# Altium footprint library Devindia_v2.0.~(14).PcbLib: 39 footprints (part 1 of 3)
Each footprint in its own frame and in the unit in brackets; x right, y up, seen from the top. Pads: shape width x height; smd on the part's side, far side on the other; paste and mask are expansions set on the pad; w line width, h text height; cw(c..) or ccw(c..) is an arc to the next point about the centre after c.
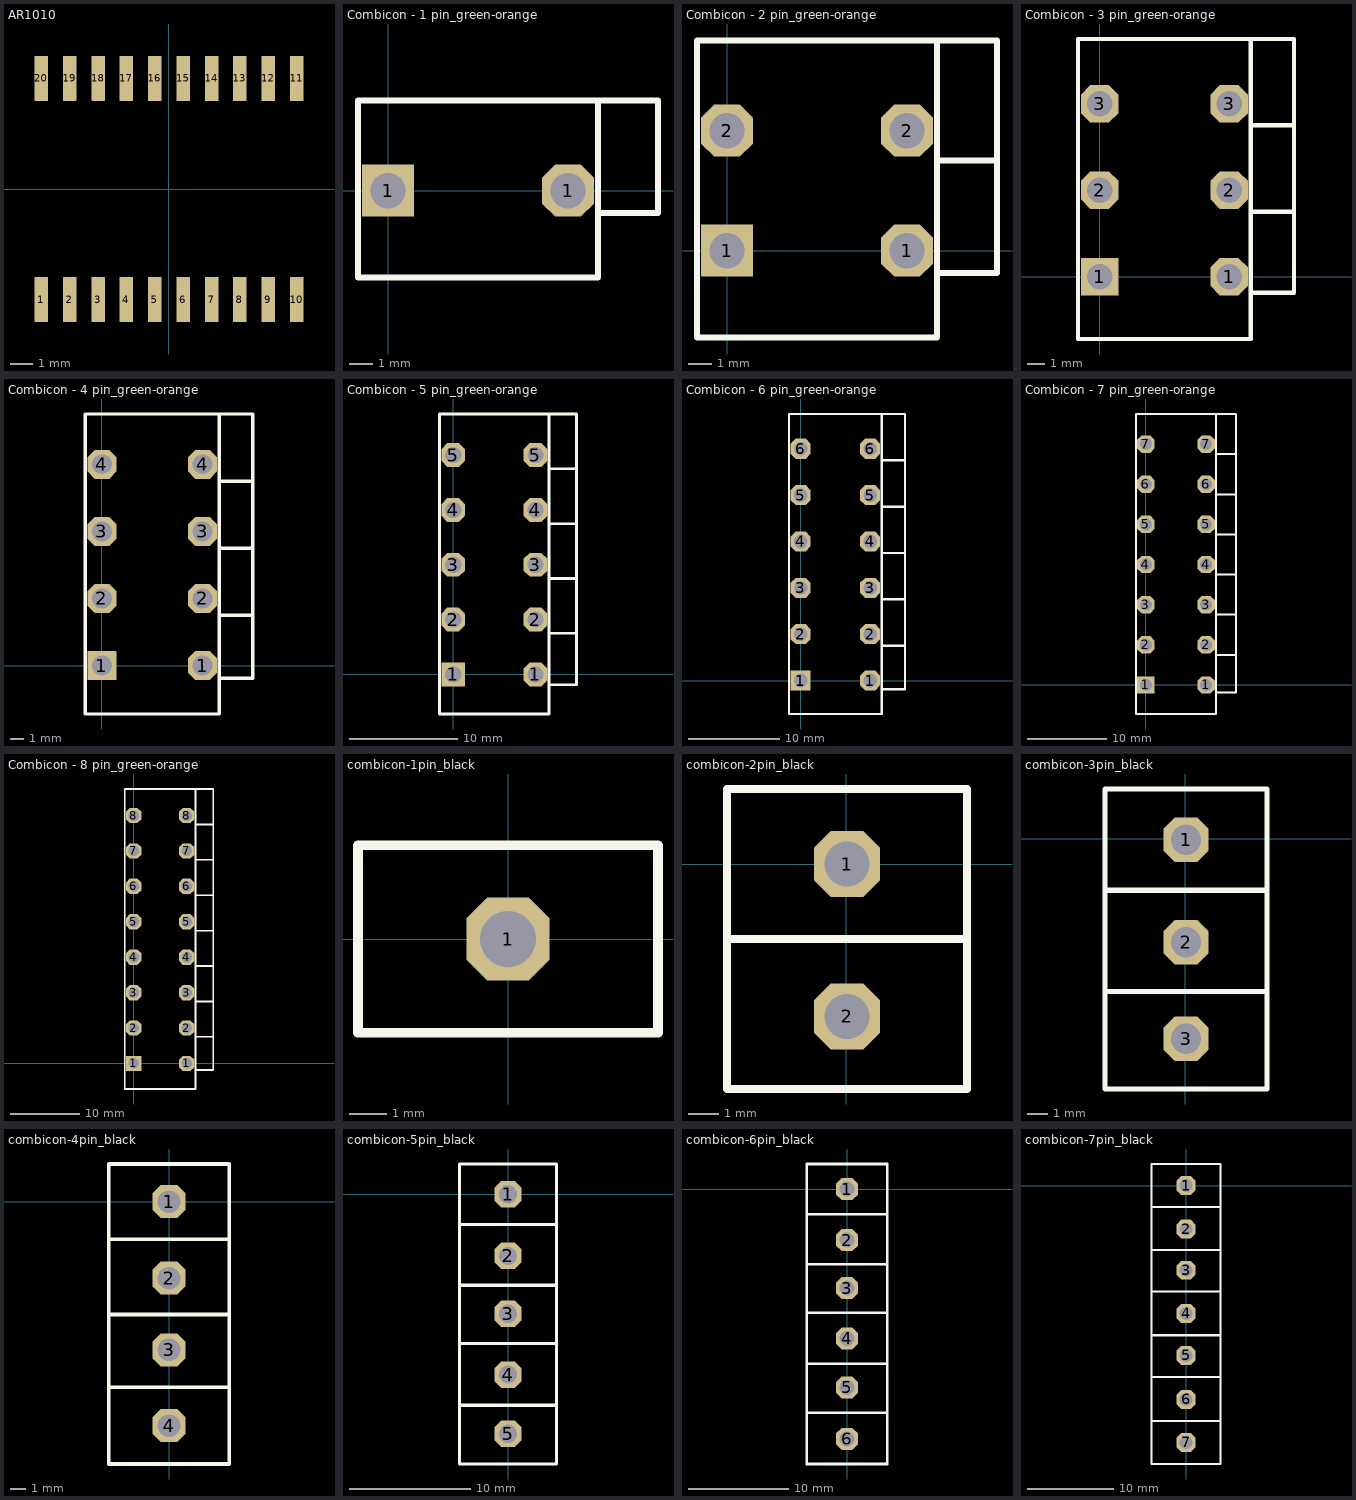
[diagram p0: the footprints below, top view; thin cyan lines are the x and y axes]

## AR1010 [mm]
pads (20):
  rect 0.6x2 smd: 1(-5.715,-4.95) 2(-4.445,-4.95) 3(-3.175,-4.95) 4(-1.905,-4.95) 5(-0.635,-4.95) 6(0.635,-4.95) 7(1.905,-4.95) 8(3.175,-4.95) 9(4.445,-4.95) 10(5.715,-4.95) 11(5.715,4.95) 12(4.445,4.95) 13(3.175,4.95) 14(1.905,4.95) 15(0.635,4.95) 16(-0.635,4.95) 17(-1.905,4.95) 18(-3.175,4.95) 19(-4.445,4.95) 20(-5.715,4.95)
Bottom Overlay:
  circle w0.254: c-5.695,-3.115 r0.284
  lines w0.254: -6.4,-3.75 6.4,-3.75 6.4,3.75 -6.4,3.75 -6.4,-3.75
3D body: height 2.05, standoff 1.05, extent -6.35,-3.175 6.35,3.175
3D body: height 1.18, standoff 0.1, extent -6.35,-3.81 6.35,3.81
3D body: height 1.16, standoff 0.84, extent -5.969,4.126 -5.461,4.445
3D body: height 0.32, standoff 0, extent -5.969,4.191 -5.461,4.51
3D body: height 1.16, standoff 0.84, extent -5.969,3.175 -5.461,4.318
3D body: height 1, standoff 0.16, extent -5.969,4.191 -5.461,4.445
3D body: height 0.32, standoff 0, extent -5.969,4.318 -5.461,5.588
3D body: height 1.16, standoff 0.84, extent -4.699,4.126 -4.191,4.445
3D body: height 0.32, standoff 0, extent -4.699,4.191 -4.191,4.51
3D body: height 1.16, standoff 0.84, extent -4.699,3.175 -4.191,4.318
3D body: height 1, standoff 0.16, extent -4.699,4.191 -4.191,4.445
3D body: height 0.32, standoff 0, extent -4.699,4.318 -4.191,5.588
3D body: height 1.16, standoff 0.84, extent -3.429,3.175 -2.921,4.318
3D body: height 1.16, standoff 0.84, extent -3.429,4.126 -2.921,4.445
3D body: height 0.32, standoff 0, extent -3.429,4.191 -2.921,4.51
3D body: height 1, standoff 0.16, extent -3.429,4.191 -2.921,4.445
3D body: height 0.32, standoff 0, extent -3.429,4.318 -2.921,5.588
3D body: height 1.16, standoff 0.84, extent -2.159,3.175 -1.651,4.318
3D body: height 1.16, standoff 0.84, extent -2.159,4.126 -1.651,4.445
3D body: height 0.32, standoff 0, extent -2.159,4.191 -1.651,4.51
3D body: height 1, standoff 0.16, extent -2.159,4.191 -1.651,4.445
3D body: height 0.32, standoff 0, extent -2.159,4.318 -1.651,5.588
3D body: height 1.16, standoff 0.84, extent -0.889,3.175 -0.381,4.318
3D body: height 1.16, standoff 0.84, extent -0.889,4.126 -0.381,4.445
3D body: height 0.32, standoff 0, extent -0.889,4.191 -0.381,4.51
3D body: height 1, standoff 0.16, extent -0.889,4.191 -0.381,4.445
3D body: height 0.32, standoff 0, extent -0.889,4.318 -0.381,5.588
3D body: height 1.16, standoff 0.84, extent 0.381,3.175 0.889,4.318
3D body: height 1.16, standoff 0.84, extent 0.381,4.126 0.889,4.445
3D body: height 0.32, standoff 0, extent 0.381,4.191 0.889,4.51
3D body: height 1, standoff 0.16, extent 0.381,4.191 0.889,4.445
3D body: height 0.32, standoff 0, extent 0.381,4.318 0.889,5.588
3D body: height 1.16, standoff 0.84, extent 1.651,3.175 2.159,4.318
3D body: height 1.16, standoff 0.84, extent 1.651,4.126 2.159,4.445
3D body: height 0.32, standoff 0, extent 1.651,4.191 2.159,4.51
3D body: height 1, standoff 0.16, extent 1.651,4.191 2.159,4.445
3D body: height 0.32, standoff 0, extent 1.651,4.318 2.159,5.588
3D body: height 1.16, standoff 0.84, extent 2.921,3.175 3.429,4.318
3D body: height 1.16, standoff 0.84, extent 2.921,4.126 3.429,4.445
3D body: height 0.32, standoff 0, extent 2.921,4.191 3.429,4.51
3D body: height 1, standoff 0.16, extent 2.921,4.191 3.429,4.445
3D body: height 0.32, standoff 0, extent 2.921,4.318 3.429,5.588
3D body: height 1.16, standoff 0.84, extent 4.191,3.175 4.699,4.318
3D body: height 1.16, standoff 0.84, extent 4.191,4.126 4.699,4.445
3D body: height 0.32, standoff 0, extent 4.191,4.191 4.699,4.51
3D body: height 1, standoff 0.16, extent 4.191,4.191 4.699,4.445
3D body: height 0.32, standoff 0, extent 4.191,4.318 4.699,5.588
3D body: height 1.16, standoff 0.84, extent 5.461,3.175 5.969,4.318
3D body: height 1.16, standoff 0.84, extent 5.461,4.126 5.969,4.445
3D body: height 0.32, standoff 0, extent 5.461,4.191 5.969,4.51
3D body: height 1, standoff 0.16, extent 5.461,4.191 5.969,4.445
3D body: height 0.32, standoff 0, extent 5.461,4.318 5.969,5.588
3D body: height 1.16, standoff 0.84, extent 5.461,-4.318 5.969,-3.175
3D body: height 1.16, standoff 0.84, extent 5.461,-4.445 5.969,-4.126
3D body: height 0.32, standoff 0, extent 5.461,-4.51 5.969,-4.191
3D body: height 1, standoff 0.16, extent 5.461,-4.445 5.969,-4.191
3D body: height 0.32, standoff 0, extent 5.461,-5.588 5.969,-4.318
3D body: height 1.16, standoff 0.84, extent 4.191,-4.318 4.699,-3.175
3D body: height 1.16, standoff 0.84, extent 4.191,-4.445 4.699,-4.126
3D body: height 0.32, standoff 0, extent 4.191,-4.51 4.699,-4.191
3D body: height 1, standoff 0.16, extent 4.191,-4.445 4.699,-4.191
3D body: height 0.32, standoff 0, extent 4.191,-5.588 4.699,-4.318
3D body: height 1.16, standoff 0.84, extent 2.921,-4.318 3.429,-3.175
3D body: height 1.16, standoff 0.84, extent 2.921,-4.445 3.429,-4.126
3D body: height 0.32, standoff 0, extent 2.921,-4.51 3.429,-4.191
3D body: height 1, standoff 0.16, extent 2.921,-4.445 3.429,-4.191
3D body: height 0.32, standoff 0, extent 2.921,-5.588 3.429,-4.318
3D body: height 1.16, standoff 0.84, extent 1.651,-4.318 2.159,-3.175
3D body: height 1.16, standoff 0.84, extent 1.651,-4.445 2.159,-4.126
3D body: height 0.32, standoff 0, extent 1.651,-4.51 2.159,-4.191
3D body: height 1, standoff 0.16, extent 1.651,-4.445 2.159,-4.191
3D body: height 0.32, standoff 0, extent 1.651,-5.588 2.159,-4.318
3D body: height 1.16, standoff 0.84, extent 0.381,-4.318 0.889,-3.175
3D body: height 1.16, standoff 0.84, extent 0.381,-4.445 0.889,-4.126
3D body: height 0.32, standoff 0, extent 0.381,-4.51 0.889,-4.191
3D body: height 1, standoff 0.16, extent 0.381,-4.445 0.889,-4.191
3D body: height 0.32, standoff 0, extent 0.381,-5.588 0.889,-4.318
3D body: height 1.16, standoff 0.84, extent -0.889,-4.318 -0.381,-3.175
3D body: height 1.16, standoff 0.84, extent -0.889,-4.445 -0.381,-4.126
3D body: height 0.32, standoff 0, extent -0.889,-4.51 -0.381,-4.191
3D body: height 1, standoff 0.16, extent -0.889,-4.445 -0.381,-4.191
3D body: height 0.32, standoff 0, extent -0.889,-5.588 -0.381,-4.318
3D body: height 1.16, standoff 0.84, extent -2.159,-4.318 -1.651,-3.175
3D body: height 1.16, standoff 0.84, extent -2.159,-4.445 -1.651,-4.126
3D body: height 0.32, standoff 0, extent -2.159,-4.51 -1.651,-4.191
3D body: height 1, standoff 0.16, extent -2.159,-4.445 -1.651,-4.191
3D body: height 0.32, standoff 0, extent -2.159,-5.588 -1.651,-4.318
3D body: height 1.16, standoff 0.84, extent -3.429,-4.318 -2.921,-3.175
3D body: height 1.16, standoff 0.84, extent -3.429,-4.445 -2.921,-4.126
3D body: height 0.32, standoff 0, extent -3.429,-4.51 -2.921,-4.191
3D body: height 1, standoff 0.16, extent -3.429,-4.445 -2.921,-4.191
3D body: height 0.32, standoff 0, extent -3.429,-5.588 -2.921,-4.318
3D body: height 1.16, standoff 0.84, extent -4.699,-4.318 -4.191,-3.175
3D body: height 1.16, standoff 0.84, extent -4.699,-4.445 -4.191,-4.126
3D body: height 0.32, standoff 0, extent -4.699,-4.51 -4.191,-4.191
3D body: height 1, standoff 0.16, extent -4.699,-4.445 -4.191,-4.191
3D body: height 0.32, standoff 0, extent -4.699,-5.588 -4.191,-4.318
3D body: height 1.16, standoff 0.84, extent -5.969,-4.318 -5.461,-3.175
3D body: height 1.16, standoff 0.84, extent -5.969,-4.445 -5.461,-4.126
3D body: height 0.32, standoff 0, extent -5.969,-4.51 -5.461,-4.191
3D body: height 1, standoff 0.16, extent -5.969,-4.445 -5.461,-4.191
3D body: height 0.32, standoff 0, extent -5.969,-5.588 -5.461,-4.318
3D body: height 2.15, standoff 2.05, extent -5.969,-2.54 -5.46,-2.034

## Combicon - 1 pin_green-orange [mm]
pads (2):
  rect 2.2x2.2 hole 1.5: 1(0,0)
  oct 2.2x2.2 hole 1.5: 1(7.62,0)
Top Overlay:
  lines w0.254: 8.956,-0.95 11.43,-0.95 11.43,3.81 8.89,3.81 ; 8.89,3.81 -1.27,3.81 -1.27,0.07 -1.27,-3.67 8.89,-3.67 8.89,3.81
3D body: height 13.66, standoff 7.75, extent 8.89,-1.016 11.43,3.81
3D body: height 13.5, standoff 13, extent 5.969,-1.503 8.864,1.397
3D body: height 13, standoff 0, extent -1.27,-3.683 8.89,3.81

## Combicon - 2 pin_green-orange [mm]
pads (4):
  rect 2.2x2.2 hole 1.5: 1(0,0)
  oct 2.2x2.2 hole 1.5: 1(7.62,0) 2(0,5.08) 2(7.62,5.08)
Top Overlay:
  lines w0.254: 8.956,-0.95 11.43,-0.95 11.43,3.81 ; 8.89,3.81 8.89,8.89 ; 8.89,3.81 8.89,-3.67 -1.27,-3.67 -1.27,0.07 -1.27,8.89 8.89,8.89 ; 8.89,3.81 11.43,3.81 ; 8.89,8.89 11.43,8.89 11.43,3.81
3D body: height 13, standoff 0, extent -1.27,-3.683 8.89,8.89
3D body: height 13.5, standoff 13, extent 5.969,-1.503 8.864,1.397
3D body: height 13.5, standoff 13, extent 5.969,3.577 8.864,6.477
3D body: height 13.66, standoff 7.75, extent 8.89,4.064 11.43,8.89
3D body: height 13.66, standoff 7.75, extent 8.89,-1.016 11.43,3.81

## Combicon - 3 pin_green-orange [mm]
pads (6):
  rect 2.2x2.2 hole 1.5: 1(0,0)
  oct 2.2x2.2 hole 1.5: 1(7.62,0) 2(0,5.08) 2(7.62,5.08) 3(0,10.16) 3(7.62,10.16)
Top Overlay:
  lines w0.254: 8.89,8.89 11.43,8.89 ; 8.956,-0.95 11.43,-0.95 11.43,3.81 ; 8.89,3.81 8.89,13.97 ; 8.89,3.81 8.89,-3.67 -1.27,-3.67 -1.27,0.07 -1.27,13.97 8.89,13.97 ; 8.89,3.81 11.43,3.81 ; 8.89,13.97 11.43,13.97 11.43,8.89 ; 11.43,3.81 11.43,8.89
3D body: height 13, standoff 0, extent -1.27,-3.683 8.89,13.97
3D body: height 13.5, standoff 13, extent 5.969,-1.503 8.864,1.397
3D body: height 13.5, standoff 13, extent 5.969,3.577 8.864,6.477
3D body: height 13.5, standoff 13, extent 5.969,8.657 8.864,11.557
3D body: height 13.66, standoff 7.75, extent 8.89,9.144 11.43,13.97
3D body: height 13.66, standoff 7.75, extent 8.89,4.064 11.43,8.89
3D body: height 13.66, standoff 7.75, extent 8.89,-1.016 11.43,3.81

## Combicon - 4 pin_green-orange [mm]
pads (8):
  rect 2.2x2.2 hole 1.5: 1(0,0)
  oct 2.2x2.2 hole 1.5: 1(7.62,0) 2(0,5.08) 2(7.62,5.08) 3(0,10.16) 3(7.62,10.16) 4(0,15.24) 4(7.62,15.24)
Top Overlay:
  lines w0.254: 8.89,8.89 11.43,8.89 ; 8.89,13.97 11.43,13.97 ; 8.956,-0.95 11.43,-0.95 11.43,3.81 ; 8.89,3.81 8.89,19.05 ; 8.89,3.81 8.89,-3.67 -1.27,-3.67 -1.27,0.07 -1.27,19.05 8.89,19.05 ; 8.89,3.81 11.43,3.81 ; 8.89,19.05 11.43,19.05 11.43,13.97 ; 11.43,3.81 11.43,8.89 ; 11.43,8.89 11.43,13.97
3D body: height 13, standoff 0, extent -1.27,-3.683 8.89,19.05
3D body: height 13.5, standoff 13, extent 5.969,-1.503 8.864,1.397
3D body: height 13.5, standoff 13, extent 5.969,3.577 8.864,6.477
3D body: height 13.5, standoff 13, extent 5.969,8.657 8.864,11.557
3D body: height 13.5, standoff 13, extent 5.969,13.737 8.864,16.637
3D body: height 13.66, standoff 7.75, extent 8.89,14.224 11.43,19.05
3D body: height 13.66, standoff 7.75, extent 8.89,9.144 11.43,13.97
3D body: height 13.66, standoff 7.75, extent 8.89,4.064 11.43,8.89
3D body: height 13.66, standoff 7.75, extent 8.89,-1.016 11.43,3.81

## Combicon - 5 pin_green-orange [mm]
pads (10):
  rect 2.2x2.2 hole 1.5: 1(0,0)
  oct 2.2x2.2 hole 1.5: 1(7.62,0) 2(0,5.08) 2(7.62,5.08) 3(0,10.16) 3(7.62,10.16) 4(0,15.24) 4(7.62,15.24) 5(0,20.32) 5(7.62,20.32)
Top Overlay:
  lines w0.254: 8.89,8.89 11.43,8.89 ; 8.89,13.97 11.43,13.97 ; 8.89,19.05 11.43,19.05 ; 8.956,-0.95 11.43,-0.95 11.43,3.81 ; 8.89,3.81 11.43,3.81 ; 8.89,3.81 8.89,-3.67 -1.27,-3.67 -1.27,0.07 -1.27,24.13 8.89,24.13 ; 8.89,3.81 8.89,24.13 ; 8.89,24.13 11.43,24.13 11.43,19.05 ; 11.43,3.81 11.43,8.89 ; 11.43,8.89 11.43,13.97 ; 11.43,13.97 11.43,19.05
3D body: height 13.66, standoff 7.75, extent 8.89,-1.016 11.43,3.81
3D body: height 13.66, standoff 7.75, extent 8.89,4.064 11.43,8.89
3D body: height 13.66, standoff 7.75, extent 8.89,9.144 11.43,13.97
3D body: height 13.66, standoff 7.75, extent 8.89,14.224 11.43,19.05
3D body: height 13.66, standoff 7.75, extent 8.89,19.304 11.43,24.13
3D body: height 13.5, standoff 13, extent 5.969,18.817 8.864,21.717
3D body: height 13.5, standoff 13, extent 5.969,13.737 8.864,16.637
3D body: height 13.5, standoff 13, extent 5.969,8.657 8.864,11.557
3D body: height 13.5, standoff 13, extent 5.969,3.577 8.864,6.477
3D body: height 13.5, standoff 13, extent 5.969,-1.503 8.864,1.397
3D body: height 13, standoff 0, extent -1.27,-3.683 8.89,24.13

## Combicon - 6 pin_green-orange [mm]
pads (12):
  rect 2.2x2.2 hole 1.5: 1(0,0)
  oct 2.2x2.2 hole 1.5: 1(7.62,0) 2(0,5.08) 2(7.62,5.08) 3(0,10.16) 3(7.62,10.16) 4(0,15.24) 4(7.62,15.24) 5(0,20.32) 5(7.62,20.32) 6(0,25.4) 6(7.62,25.4)
Top Overlay:
  lines w0.254: 8.89,8.89 11.43,8.89 ; 8.89,13.97 11.43,13.97 ; 8.89,19.05 11.43,19.05 ; 8.89,24.13 11.43,24.13 ; 8.956,-0.95 11.43,-0.95 11.43,3.81 ; 8.89,3.81 8.89,29.21 ; 8.89,3.81 8.89,-3.67 -1.27,-3.67 -1.27,0.07 -1.27,29.21 8.89,29.21 ; 8.89,3.81 11.43,3.81 ; 8.89,29.21 11.43,29.21 11.43,24.13 ; 11.43,3.81 11.43,8.89 ; 11.43,8.89 11.43,13.97 ; 11.43,13.97 11.43,19.05 ; 11.43,19.05 11.43,24.13
3D body: height 13, standoff 0, extent -1.27,-3.683 8.89,29.21
3D body: height 13.5, standoff 13, extent 5.969,-1.503 8.864,1.397
3D body: height 13.5, standoff 13, extent 5.969,3.577 8.864,6.477
3D body: height 13.5, standoff 13, extent 5.969,8.657 8.864,11.557
3D body: height 13.5, standoff 13, extent 5.969,13.737 8.864,16.637
3D body: height 13.5, standoff 13, extent 5.969,18.817 8.864,21.717
3D body: height 13.5, standoff 13, extent 5.969,23.897 8.864,26.797
3D body: height 13.66, standoff 7.75, extent 8.89,24.384 11.43,29.21
3D body: height 13.66, standoff 7.75, extent 8.89,19.304 11.43,24.13
3D body: height 13.66, standoff 7.75, extent 8.89,14.224 11.43,19.05
3D body: height 13.66, standoff 7.75, extent 8.89,9.144 11.43,13.97
3D body: height 13.66, standoff 7.75, extent 8.89,4.064 11.43,8.89
3D body: height 13.66, standoff 7.75, extent 8.89,-1.016 11.43,3.81

## Combicon - 7 pin_green-orange [mm]
pads (14):
  rect 2.2x2.2 hole 1.5: 1(0,0)
  oct 2.2x2.2 hole 1.5: 1(7.62,0) 2(0,5.08) 2(7.62,5.08) 3(0,10.16) 3(7.62,10.16) 4(0,15.24) 4(7.62,15.24) 5(0,20.32) 5(7.62,20.32) 6(0,25.4) 6(7.62,25.4) 7(0,30.48) 7(7.62,30.48)
Top Overlay:
  lines w0.254: 8.89,8.89 11.43,8.89 ; 8.89,13.97 11.43,13.97 ; 8.89,19.05 11.43,19.05 ; 8.89,24.13 11.43,24.13 ; 8.89,29.21 11.43,29.21 ; 8.956,-0.95 11.43,-0.95 11.43,3.81 ; 8.89,3.81 11.43,3.81 ; 8.89,3.81 8.89,-3.67 -1.27,-3.67 -1.27,0.07 -1.27,34.29 8.89,34.29 ; 8.89,3.81 8.89,34.29 ; 8.89,34.29 11.43,34.29 ; 8.89,34.29 11.43,34.29 ; 11.43,3.81 11.43,8.89 ; 11.43,8.89 11.43,13.97 ; 11.43,13.97 11.43,19.05 ; 11.43,19.05 11.43,24.13 ; 11.43,24.13 11.43,29.21 ; 11.43,29.21 11.43,34.29
3D body: height 13.66, standoff 7.75, extent 8.89,-1.016 11.43,3.81
3D body: height 13.66, standoff 7.75, extent 8.89,4.064 11.43,8.89
3D body: height 13.66, standoff 7.75, extent 8.89,9.144 11.43,13.97
3D body: height 13.66, standoff 7.75, extent 8.89,14.224 11.43,19.05
3D body: height 13.66, standoff 7.75, extent 8.89,19.304 11.43,24.13
3D body: height 13.66, standoff 7.75, extent 8.89,24.384 11.43,29.21
3D body: height 13.66, standoff 7.75, extent 9.017,29.464 11.557,34.29
3D body: height 13.5, standoff 13, extent 5.969,28.977 8.864,31.877
3D body: height 13.5, standoff 13, extent 5.969,23.897 8.864,26.797
3D body: height 13.5, standoff 13, extent 5.969,18.817 8.864,21.717
3D body: height 13.5, standoff 13, extent 5.969,13.737 8.864,16.637
3D body: height 13.5, standoff 13, extent 5.969,8.657 8.864,11.557
3D body: height 13.5, standoff 13, extent 5.969,3.577 8.864,6.477
3D body: height 13.5, standoff 13, extent 5.969,-1.503 8.864,1.397
3D body: height 13, standoff 0, extent -1.27,-3.683 8.89,34.29

## Combicon - 8 pin_green-orange [mm]
pads (16):
  rect 2.2x2.2 hole 1.5: 1(0,0)
  oct 2.2x2.2 hole 1.5: 1(7.62,0) 2(0,5.08) 2(7.62,5.08) 3(0,10.16) 3(7.62,10.16) 4(0,15.24) 4(7.62,15.24) 5(0,20.32) 5(7.62,20.32) 6(0,25.4) 6(7.62,25.4) 7(0,30.48) 7(7.62,30.48) 8(0,35.56) 8(7.62,35.56)
Top Overlay:
  lines w0.254: 8.89,8.89 11.43,8.89 ; 8.89,13.97 11.43,13.97 ; 8.89,19.05 11.43,19.05 ; 8.89,24.13 11.43,24.13 ; 8.89,29.21 11.43,29.21 ; 8.89,34.29 11.43,34.29 ; 8.956,-0.95 11.43,-0.95 11.43,3.81 ; 8.89,3.81 11.43,3.81 ; 8.89,3.81 8.89,-3.67 -1.27,-3.67 -1.27,0.07 -1.27,39.37 8.89,39.37 ; 8.89,3.81 8.89,39.37 ; 8.89,39.37 11.43,39.37 11.43,34.29 ; 11.43,3.81 11.43,8.89 ; 11.43,8.89 11.43,13.97 ; 11.43,13.97 11.43,19.05 ; 11.43,19.05 11.43,24.13 ; 11.43,24.13 11.43,29.21 ; 11.43,29.21 11.43,34.29
3D body: height 13.66, standoff 7.75, extent 8.89,-1.016 11.43,3.81
3D body: height 13.66, standoff 7.75, extent 8.89,4.064 11.43,8.89
3D body: height 13.66, standoff 7.75, extent 8.89,9.144 11.43,13.97
3D body: height 13.66, standoff 7.75, extent 8.89,14.224 11.43,19.05
3D body: height 13.66, standoff 7.75, extent 8.89,19.304 11.43,24.13
3D body: height 13.66, standoff 7.75, extent 8.89,24.384 11.43,29.21
3D body: height 13.66, standoff 7.75, extent 9.017,29.464 11.557,34.29
3D body: height 13.66, standoff 7.75, extent 8.89,34.544 11.43,39.37
3D body: height 13.5, standoff 13, extent 5.969,34.057 8.864,36.957
3D body: height 13.5, standoff 13, extent 5.969,28.977 8.864,31.877
3D body: height 13.5, standoff 13, extent 5.969,23.897 8.864,26.797
3D body: height 13.5, standoff 13, extent 5.969,18.817 8.864,21.717
3D body: height 13.5, standoff 13, extent 5.969,13.737 8.864,16.637
3D body: height 13.5, standoff 13, extent 5.969,8.657 8.864,11.557
3D body: height 13.5, standoff 13, extent 5.969,3.577 8.864,6.477
3D body: height 13.5, standoff 13, extent 5.969,-1.503 8.864,1.397
3D body: height 13, standoff 0, extent -1.27,-3.683 8.89,39.37

## combicon-1pin_black [mm]
pads (1):
  oct 2.2x2.2 hole 1.5: 1(0,0)
Top Overlay:
  lines w0.254: -4,-2.5 4,-2.5 4,2.5 -4,2.5 -4,-2.45
3D body: height 12.9, standoff 12.4, extent -1.778,-1.905 2.007,1.887
3D body: height 12.4, standoff 8.5, extent -2.667,-2.5 3.937,2.413
3D body: height 8.5, standoff 0, extent -3.937,-2.413 3.937,2.413

## combicon-2pin_black [mm]
pads (2):
  oct 2.2x2.2 hole 1.5: 1(0.025,0) 2(0.025,-5.08)
Top Overlay:
  lines w0.254: -3.975,-2.5 4.025,-2.5 ; -3.975,-7.5 -3.975,2.5 4.025,2.5 4.025,-7.5 -3.975,-7.5
3D body: height 12.9, standoff 12.4, extent -1.753,-1.905 2.032,1.887
3D body: height 12.9, standoff 12.4, extent -1.88,-6.731 1.905,-2.939
3D body: height 12.4, standoff 8.5, extent -2.642,-7.507 3.978,2.413
3D body: height 8.5, standoff 0, extent -3.912,-7.493 3.962,-2.413
3D body: height 8.5, standoff 0, extent -3.912,-2.413 3.962,2.413

## combicon-3pin_black [mm]
pads (3):
  oct 2.2x2.2 hole 1.5: 1(0.025,-0.05) 2(0.025,-5.13) 3(0.025,-9.9)
Top Overlay:
  lines w0.254: -3.975,-2.55 4.025,-2.55 ; -3.975,-7.55 4.025,-7.55 ; -3.975,-7.55 -3.975,2.45 4.025,2.45 4.025,-7.55 ; -3.975,-7.55 -3.975,-12.375 4.025,-12.375 4.025,-7.55
3D body: height 8.5, standoff 0, extent -3.912,-2.463 3.962,2.363
3D body: height 8.5, standoff 0, extent -3.912,-7.543 3.962,-2.463
3D body: height 12.4, standoff 8.5, extent -2.644,-12.387 3.985,2.363
3D body: height 12.9, standoff 12.4, extent -1.88,-6.781 1.905,-2.989
3D body: height 12.9, standoff 12.4, extent -1.753,-1.955 2.032,1.837
3D body: height 8.5, standoff 0, extent -3.912,-12.369 3.962,-7.543
3D body: height 12.9, standoff 12.4, extent -1.828,-11.83 1.957,-8.037

## combicon-4pin_black [mm]
pads (4):
  oct 2.2x2.2 hole 1.5: 1(0,0) 2(0,-5.08) 3(0,-9.85) 4(0,-14.875)
Top Overlay:
  lines w0.254: -4,-12.325 4,-12.325 ; -4,-2.5 4,-2.5 ; -4,-7.5 -4,-17.4 -3.975,-17.425 4,-17.425 4,-7.5 ; -4,-7.5 -4,2.5 4,2.5 4,-7.5 ; -4,-7.5 4,-7.5
3D body: height 12.9, standoff 12.4, extent -1.828,-16.755 1.957,-12.963
3D body: height 12.9, standoff 12.4, extent -1.853,-11.78 1.932,-7.987
3D body: height 8.5, standoff 0, extent -3.937,-12.319 3.937,-7.493
3D body: height 8.5, standoff 0, extent -3.937,-17.399 3.937,-12.319
3D body: height 12.9, standoff 12.4, extent -1.778,-1.905 2.007,1.887
3D body: height 12.9, standoff 12.4, extent -1.905,-6.731 1.88,-2.939
3D body: height 12.4, standoff 8.5, extent -2.671,-17.357 3.968,2.413
3D body: height 8.5, standoff 0, extent -3.937,-7.493 3.937,-2.413
3D body: height 8.5, standoff 0, extent -3.937,-2.413 3.937,2.413

## combicon-5pin_black [mm]
pads (5):
  oct 2.2x2.2 hole 1.5: 1(0,0) 2(0,-5.08) 3(0,-9.85) 4(0,-14.875) 5(0,-19.75)
Top Overlay:
  lines w0.254: -4,-17.4 4,-17.4 ; -4,-12.325 4,-12.325 ; -4,-2.5 4,-2.5 ; -4,-7.5 4,-7.5 ; -4,-7.5 -4,2.5 4,2.5 4,-7.5 ; -4,-7.5 -4,-22.25 4,-22.25 4,-7.5
3D body: height 8.5, standoff 0, extent -3.937,-2.413 3.937,2.413
3D body: height 8.5, standoff 0, extent -3.937,-7.493 3.937,-2.413
3D body: height 12.4, standoff 8.5, extent -2.673,-22.262 3.976,2.413
3D body: height 12.9, standoff 12.4, extent -1.905,-6.731 1.88,-2.939
3D body: height 12.9, standoff 12.4, extent -1.778,-1.905 2.007,1.887
3D body: height 8.5, standoff 0, extent -3.937,-17.399 3.937,-12.319
3D body: height 8.5, standoff 0, extent -3.937,-12.319 3.937,-7.493
3D body: height 8.5, standoff 0, extent -3.937,-22.225 3.937,-17.399
3D body: height 12.9, standoff 12.4, extent -1.853,-11.78 1.932,-7.987
3D body: height 12.9, standoff 12.4, extent -1.828,-16.755 1.957,-12.963
3D body: height 12.9, standoff 12.4, extent -1.803,-21.73 1.982,-17.938

## combicon-6pin_black [mm]
pads (6):
  oct 2.2x2.2 hole 1.5: 1(0,0) 2(0,-5.08) 3(0,-9.85) 4(0,-14.875) 5(0,-19.75) 6(0,-24.875)
Top Overlay:
  lines w0.254: -4,-27.375 -4,-27.3 -4,-7.5 ; -4,-22.25 4,-22.25 ; -4,-17.4 4,-17.4 ; -4,-12.325 4,-12.325 ; -4,-2.5 4,-2.5 ; -3.925,-27.375 4,-27.375 4,-7.5 ; -4,-7.5 4,-7.5 ; -4,-7.5 -4,2.5 4,2.5 4,-7.5
3D body: height 8.5, standoff 0, extent -3.937,-2.413 3.937,2.413
3D body: height 8.5, standoff 0, extent -3.937,-7.493 3.937,-2.413
3D body: height 12.4, standoff 8.5, extent -2.675,-27.379 3.984,2.413
3D body: height 12.9, standoff 12.4, extent -1.905,-6.731 1.88,-2.939
3D body: height 12.9, standoff 12.4, extent -1.778,-1.905 2.007,1.887
3D body: height 8.5, standoff 0, extent -3.937,-17.399 3.937,-12.319
3D body: height 8.5, standoff 0, extent -3.937,-12.319 3.937,-7.493
3D body: height 8.5, standoff 0, extent -3.937,-27.305 3.937,-22.225
3D body: height 8.5, standoff 0, extent -3.937,-22.225 3.937,-17.399
3D body: height 12.9, standoff 12.4, extent -1.853,-11.78 1.932,-7.987
3D body: height 12.9, standoff 12.4, extent -1.828,-16.755 1.957,-12.963
3D body: height 12.9, standoff 12.4, extent -1.803,-21.73 1.982,-17.938
3D body: height 12.9, standoff 12.4, extent -1.803,-26.755 1.982,-22.963

## combicon-7pin_black [mm]
pads (7):
  oct 2.2x2.2 hole 1.5: 1(0,0) 2(0,-5.08) 3(0,-9.85) 4(0,-14.875) 5(0,-19.75) 6(0,-24.875) 7(0,-29.875)
Top Overlay:
  lines w0.254: -4,-22.25 4,-22.25 ; -4,-17.4 4,-17.4 ; -4,-12.325 4,-12.325 ; -4,-2.5 4,-2.5 ; -3.925,-27.375 4,-27.375 ; 4,-32.375 4,-27.375 ; -4,-7.5 4,-7.5 ; -4,-7.5 -4,2.5 4,2.5 4,-7.5 ; -4,-7.5 -4,-27.3 -4,-32.375 3.95,-32.375 4,-32.325 4,-27.375 ; 4,-27.375 4,-7.5
3D body: height 8.5, standoff 0, extent -3.937,-2.413 3.937,2.413
3D body: height 8.5, standoff 0, extent -3.937,-7.493 3.937,-2.413
3D body: height 12.4, standoff 8.5, extent -2.677,-32.383 3.992,2.413
3D body: height 12.9, standoff 12.4, extent -1.905,-6.731 1.88,-2.939
3D body: height 12.9, standoff 12.4, extent -1.778,-1.905 2.007,1.887
3D body: height 8.5, standoff 0, extent -3.937,-17.399 3.937,-12.319
3D body: height 8.5, standoff 0, extent -3.937,-12.319 3.937,-7.493
3D body: height 8.5, standoff 0, extent -3.937,-27.305 3.937,-22.225
3D body: height 8.5, standoff 0, extent -3.937,-22.225 3.937,-17.399
3D body: height 12.9, standoff 12.4, extent -1.853,-11.78 1.932,-7.987
3D body: height 12.9, standoff 12.4, extent -1.828,-16.755 1.957,-12.963
3D body: height 12.9, standoff 12.4, extent -1.803,-21.73 1.982,-17.938
3D body: height 12.9, standoff 12.4, extent -1.803,-26.755 1.982,-22.963
3D body: height 8.5, standoff 0, extent -3.937,-32.33 3.937,-27.25
3D body: height 12.9, standoff 12.4, extent -1.803,-31.755 1.982,-27.963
